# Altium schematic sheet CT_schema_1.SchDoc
size 535 x 258 mm
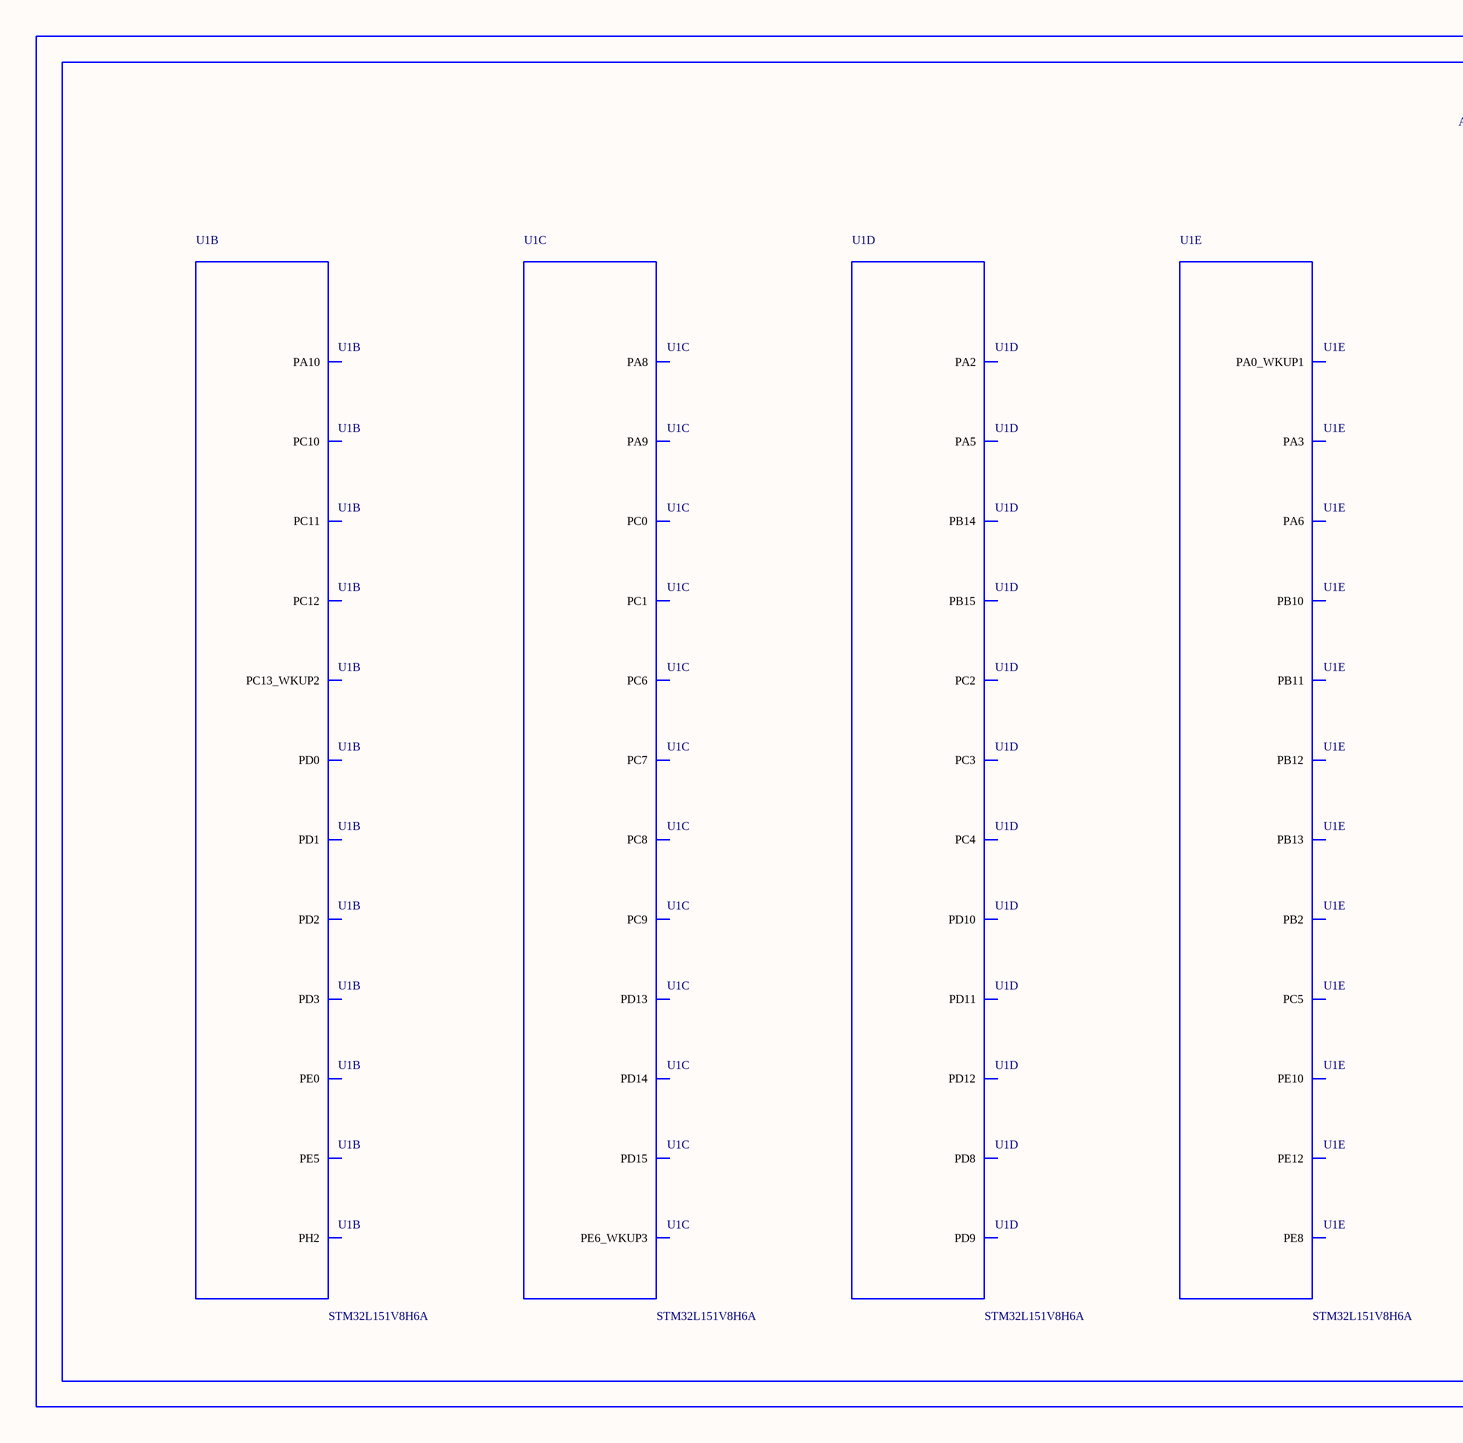
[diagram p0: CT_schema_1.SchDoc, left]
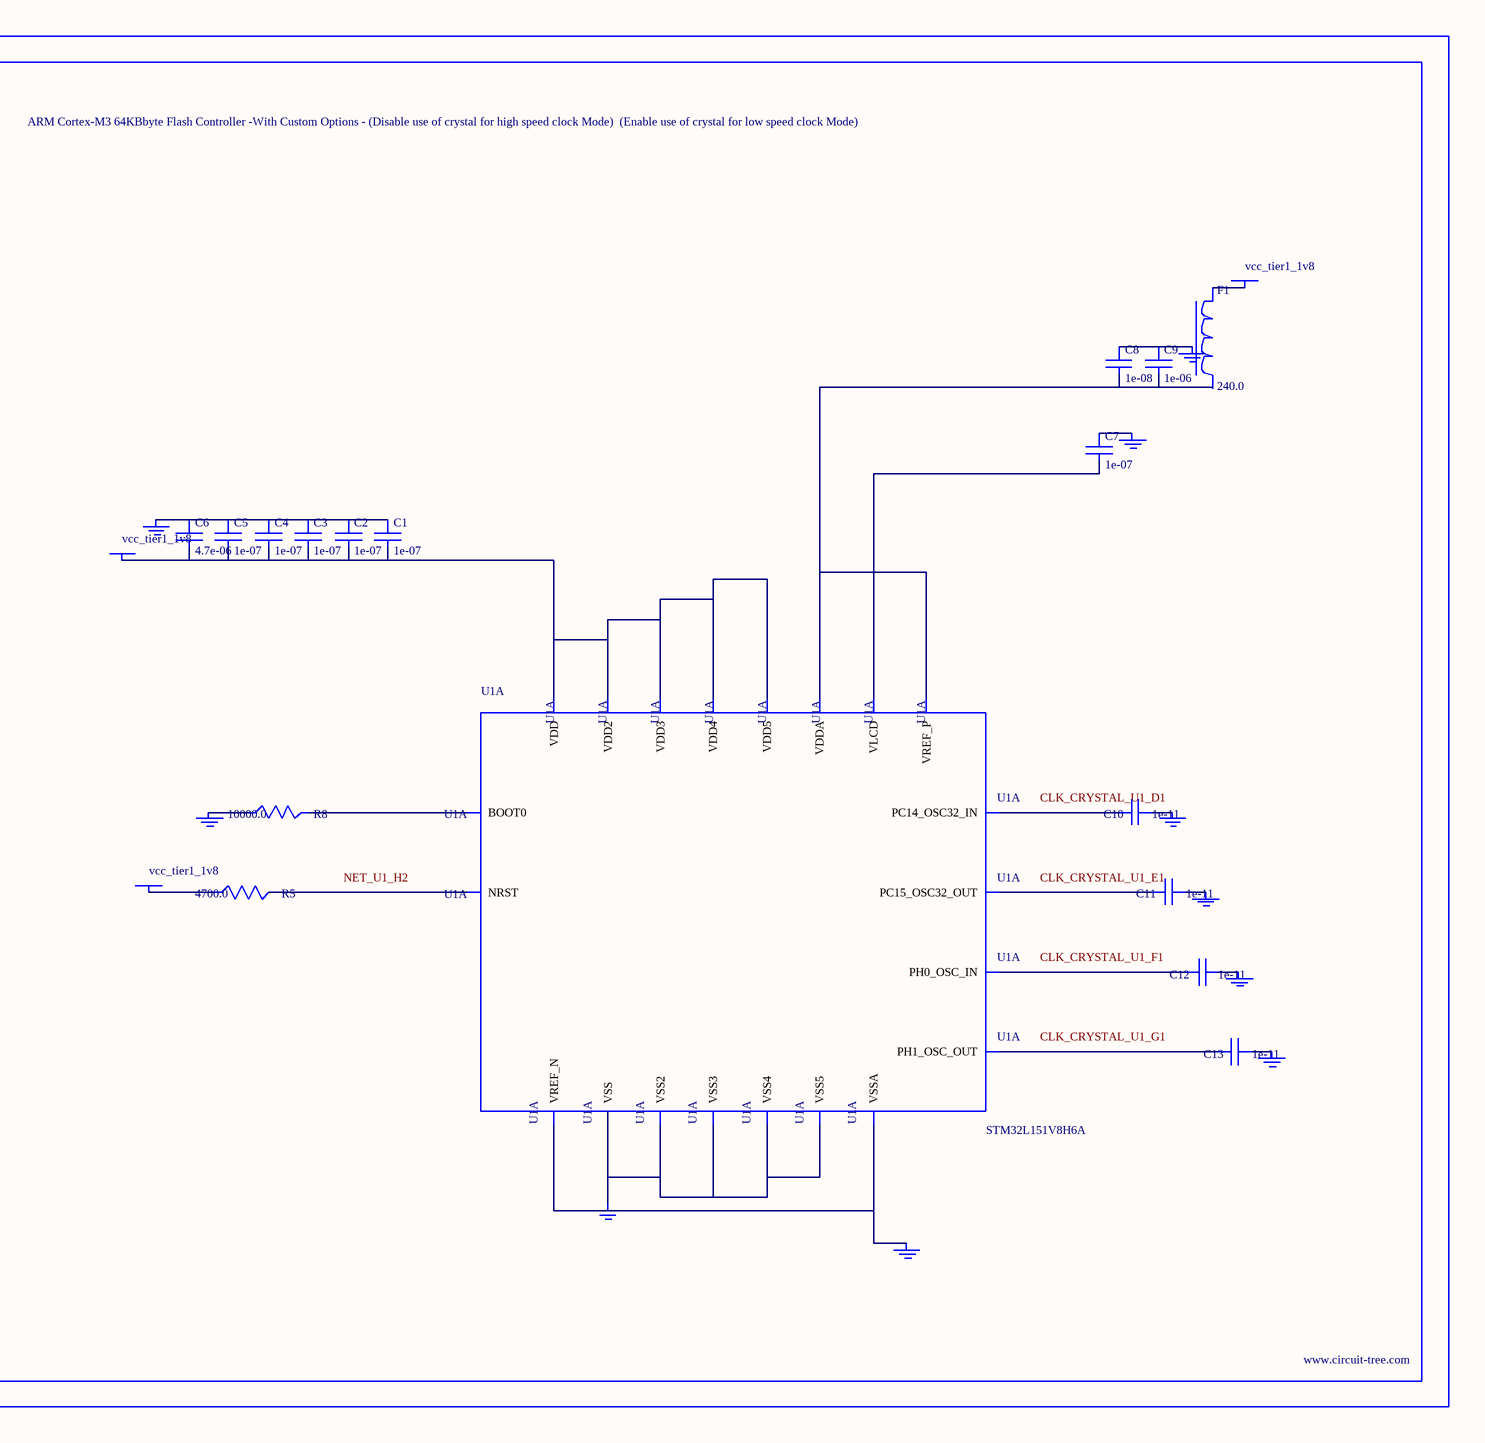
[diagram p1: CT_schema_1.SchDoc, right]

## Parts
BORDER0  (no value)
C1  1e-07  [C0603]
C2  1e-07  [C0603]
C3  1e-07  [C0603]
C4  1e-07  [C0603]
C5  1e-07  [C0603]
C6  4.7e-06  [C0603]
C7  1e-07  [C0603]
C8  1e-08  [C0603]
C9  1e-06  [C0603]
C10  1e-11  [C0402]
C11  1e-11  [C0402]
C12  1e-11  [C0402]
C13  1e-11  [C0402]
F1  240.0  [L0603]
GND_INSTANCE_0_0  (no value)
GND_INSTANCE_0_1  (no value)
GND_INSTANCE_0_2  (no value)
GND_INSTANCE_0_3  (no value)
GND_INSTANCE_0_4  (no value)
GND_INSTANCE_0_5  (no value)
GND_INSTANCE_0_6  (no value)
GND_INSTANCE_0_7  (no value)
GND_INSTANCE_0_8  (no value)
GND_INSTANCE_0_9  (no value)
POWER_INSTANCE_0_0  vcc_tier1_1v8
POWER_INSTANCE_0_1  vcc_tier1_1v8
POWER_INSTANCE_0_2  vcc_tier1_1v8
R5  4700.0  [R0603]
R8  10000.0  [R0603]
U1  STM32L151V8H6A  [UFBGA100]  (parts A,B,C,D,E of 9)

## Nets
NetC1_1: C1.1 C2.1 C3.1 C4.1 C5.1 C6.1 GND_INSTANCE_0_1.0(GND)
NetC1_2: C1.2 C2.2 C3.2 C4.2 C5.2 C6.2 POWER_INSTANCE_0_1.0(PWR) U1.C4(VDD) U1.G2(VDD4) U1.G11(VDD2) U1.G12(VDD3) U1.H3(VDD5)
NetC7_1: C7.1 GND_INSTANCE_0_2.0(GND)
NetC7_2: C7.2 U1.E2(VLCD)
NetC8_1: C8.1 C9.1 GND_INSTANCE_0_0.0(GND)
NetC8_2: C8.2 C9.2 U1.L1(VREF_P) U1.M1(VDDA)
NetC10_1: C10.1 GND_INSTANCE_0_4.0(GND)
NetC10_2: C10.2 U1.D1(PC14_OSC32_IN)
NetC11_1: C11.1 GND_INSTANCE_0_5.0(GND)
NetC11_2: C11.2 U1.E1(PC15_OSC32_OUT)
NetC12_1: C12.1 GND_INSTANCE_0_6.0(GND)
NetC12_2: C12.2 U1.F1(PH0_OSC_IN)
NetC13_1: C13.1 GND_INSTANCE_0_7.0(GND)
NetC13_2: C13.2 U1.G1(PH1_OSC_OUT)
NetF1_1: F1.1 POWER_INSTANCE_0_0.0(PWR)
NetGND_INSTANCE_0_3_0: GND_INSTANCE_0_3.0(GND) R8.1
NetGND_INSTANCE_0_8_0: GND_INSTANCE_0_8.0(GND) U1.J1(VSSA) U1.K1(VREF_N)
NetGND_INSTANCE_0_9_0: GND_INSTANCE_0_9.0(GND) U1.D3(VSS) U1.E3(VSS2) U1.F2(VSS5) U1.F11(VSS3) U1.F12(VSS4)
NetPOWER_INSTANCE_0_2_0: POWER_INSTANCE_0_2.0(PWR) R5.1
NetR5_2: R5.2 U1.H2(NRST)
NetR8_2: R8.2 U1.A4(BOOT0)

Not connected (* = marked no-connect by the designer): F1 2; U1 B8(PD3) B9(PD1) B10(PC12) B11(PC10) C1(PC13_WKUP2) C2(PE5) C3(PE0) C8(PD2) C9(PD0) C10(PC11) C11(PH2) C12(PA10) D2(PE6_WKUP3) D10(PA9) D11(PA8) D12(PC9) E10(PC8) E11(PC7) E12(PC6) H1(PC0) H10(PD15) H11(PD14) H12(PD13) J2(PC1) J3(PC2) J10(PD12) J11(PD11) J12(PD10) K2(PC3) K3(PA2) K4(PA5) K5(PC4) K8(PD9) K9(PD8) K10(PB15) K11(PB14) K12(PB13) L2(PA0_WKUP1) L3(PA3) L4(PA6) L5(PC5) L6(PB2) L7(PE8) L8(PE10) L9(PE12) L10(PB10) L11(PB11) L12(PB12)

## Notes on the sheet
- Labels drawn without touching a wire or pin: CLK_CRYSTAL_U1_D1, CLK_CRYSTAL_U1_E1, CLK_CRYSTAL_U1_F1, CLK_CRYSTAL_U1_G1, NET_U1_H2

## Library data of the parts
BORDER0 = BORDER_PAGE0
C1-C5 C7 = 06035C104K4Z2A
C6 = GRM188R6YA475KE15D
C8 = 06035C103K4Z2A
C9 = C0603C105K3RACTU
C10-C13 = C0402C100K3GACTU
F1 = Z0603C241ASMST
GND_INSTANCE_0_0-GND_INSTANCE_0_9 = GND
POWER_INSTANCE_0_0-POWER_INSTANCE_0_2 = PWR
R5 = RC0603JR-074K7L
R8 = RC0603JR-0710KL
